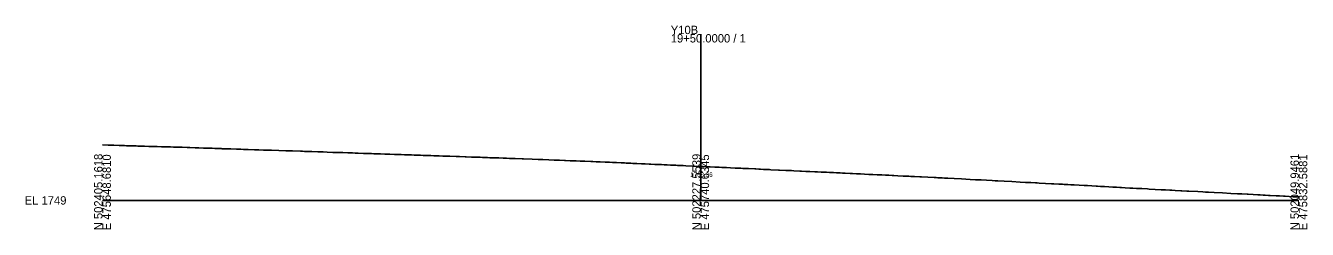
# Model space of a CAD drawing. Extents: x -26 to 1803, y -10 to 9558.
# Drawn here: x -25.7 to 402.8, y 9490.3 to 9558.5 of the extents above; entities that cross this region are included whole.
import ezdxf

# ---------------------------------------------------------------- set-up
doc = ezdxf.new("R2010")
doc.units = 0
for name, color, linetype in [('Exist Cross Section Cell', 7, 'Continuous'), ('Exist XS Center Line Elevation Label', 7, 'Continuous'), ('Exist XS Ground Line', 7, 'Continuous')]:
    doc.layers.add(name, color=color, linetype=linetype)

msp = doc.modelspace()

# ---------------------------------------------------------------- linework, layer by layer
at = {"layer": 'Exist Cross Section Cell'}
for p, q in [((200, 9500), (200, 9555.63)), ((0, 9500), (200, 9500)), ((200, 9500), (400, 9500))]:
    msp.add_line(p, q, dxfattribs=at)
at = {"layer": 'Exist XS Ground Line'}
msp.add_lwpolyline([(0, 9518.54), (1.94, 9518.49), (2.83, 9518.46), (3.78, 9518.43), (5.62, 9518.37), (7.36, 9518.32), (8.07, 9518.3), (8.44, 9518.29), (9.95, 9518.24), (11.27, 9518.2), (11.8, 9518.19), (12.83, 9518.16), (13.64, 9518.13), (14.07, 9518.12), (15.5, 9518.08), (16.91, 9518.04), (17.38, 9518.02), (18.27, 9518), (19.74, 9517.96), (21.27, 9517.91), (22.78, 9517.87), (23.7, 9517.84), (24.78, 9517.81), (25.34, 9517.79), (26.65, 9517.76), (28.33, 9517.7), (29.15, 9517.67), (31, 9517.61), (32.24, 9517.57), (33.79, 9517.52), (34.19, 9517.51), (34.58, 9517.5), (35.93, 9517.46), (36.62, 9517.43), (37.6, 9517.39), (39.27, 9517.33), (39.67, 9517.31), (40.02, 9517.3), (41.46, 9517.26), (42.22, 9517.23), (42.89, 9517.21), (44.86, 9517.14), (45.33, 9517.13), (46.27, 9517.1), (47.2, 9517.07), (48.66, 9517.02), (50.78, 9516.95), (51.4, 9516.93), (52.27, 9516.9), (53.87, 9516.85), (56.47, 9516.77), (58.92, 9516.69), (61.34, 9516.61), (61.92, 9516.59), (63.51, 9516.53), (66.25, 9516.44), (66.87, 9516.42), (67.54, 9516.39), (68.42, 9516.37), (70.02, 9516.31), (71.98, 9516.25), (72.5, 9516.23), (72.88, 9516.22), (73.73, 9516.2), (75.13, 9516.14), (76.96, 9516.08), (77.56, 9516.05), (78.28, 9516.04), (79.16, 9516.02), (80.31, 9515.97), (82.05, 9515.91), (82.68, 9515.88), (83.64, 9515.86), (84.51, 9515.83), (85.52, 9515.79), (87.26, 9515.73), (87.85, 9515.71), (88.99, 9515.68), (89.93, 9515.66), (90.71, 9515.63), (92.38, 9515.56), (92.92, 9515.55), (94.43, 9515.5), (95.31, 9515.47), (96.11, 9515.44), (97.59, 9515.38), (98.52, 9515.36), (98.97, 9515.34), (99.86, 9515.32), (100.95, 9515.28), (101.79, 9515.25), (103.29, 9515.19), (104.17, 9515.17), (104.56, 9515.15), (105.31, 9515.13), (106.34, 9515.09), (107.22, 9515.07), (108.54, 9515.01), (109.78, 9514.98), (110.73, 9514.95), (111.68, 9514.91), (112.6, 9514.88), (113.76, 9514.83), (115.67, 9514.78), (116.18, 9514.76), (118.23, 9514.68), (119.39, 9514.64), (121.26, 9514.59), (121.63, 9514.58), (123.37, 9514.5), (123.87, 9514.49), (126.28, 9514.42), (127.04, 9514.39), (128.71, 9514.32), (129.49, 9514.29), (130.51, 9514.26), (132.49, 9514.19), (133.98, 9514.13), (135.13, 9514.09), (136.08, 9514.06), (137.95, 9513.99), (140.36, 9513.9), (140.76, 9513.89), (143.63, 9513.78), (145.69, 9513.69), (146.38, 9513.67), (147.21, 9513.64), (149.25, 9513.57), (151.01, 9513.49), (152.02, 9513.46), (152.78, 9513.43), (154.5, 9513.37), (154.82, 9513.35), (156.32, 9513.27), (157.65, 9513.24), (158.35, 9513.21), (159.71, 9513.16), (160.35, 9513.13), (160.77, 9513.11), (161.29, 9513.09), (163.28, 9513), (163.9, 9512.98), (165.11, 9512.93), (165.83, 9512.9), (166.35, 9512.88), (168.11, 9512.78), (168.91, 9512.77), (169.47, 9512.74), (170.56, 9512.7), (171.26, 9512.66), (171.88, 9512.64), (173.39, 9512.56), (174.54, 9512.53), (175.04, 9512.51), (176, 9512.47), (176.66, 9512.43), (177.36, 9512.4), (178.63, 9512.33), (180.17, 9512.28), (180.6, 9512.26), (181.44, 9512.22), (182.8, 9512.16), (183.3, 9512.13), (184.72, 9512.06), (185.8, 9512.04), (186.88, 9511.99), (187.82, 9511.93), (188.76, 9511.89), (189.92, 9511.83), (191.73, 9511.76), (192.29, 9511.73), (193.09, 9511.68), (194.17, 9511.63), (195.09, 9511.58), (197.3, 9511.49), (197.74, 9511.47), (199.5, 9511.38), (200, 9511.36), (200.81, 9511.32), (201.95, 9511.26), (202.86, 9511.23), (203.17, 9511.22), (204.76, 9511.14), (206.22, 9511.07), (207.1, 9511.03), (208.61, 9510.97), (209.95, 9510.9), (211.56, 9510.83), (212.21, 9510.8), (213.38, 9510.75), (214.05, 9510.72), (216.04, 9510.62), (218.1, 9510.53), (218.48, 9510.51), (219.39, 9510.47), (220.01, 9510.44), (221.04, 9510.39), (223.05, 9510.29), (223.5, 9510.27), (225.99, 9510.16), (226.3, 9510.14), (228.48, 9510.04), (230.36, 9509.95), (231.1, 9509.91), (233.14, 9509.82), (233.68, 9509.79), (235.18, 9509.72), (235.79, 9509.69), (236.46, 9509.66), (238.17, 9509.58), (239.04, 9509.54), (240.29, 9509.48), (241.23, 9509.44), (242.1, 9509.4), (243.08, 9509.36), (244.37, 9509.29), (245.4, 9509.24), (246.66, 9509.18), (247.37, 9509.14), (247.74, 9509.12), (248.32, 9509.1), (249.96, 9509.02), (250.79, 9508.98), (252.09, 9508.92), (253.38, 9508.86), (254.75, 9508.79), (256.24, 9508.72), (256.83, 9508.69), (257.54, 9508.66), (259, 9508.59), (260.57, 9508.51), (261.81, 9508.45), (262.23, 9508.43), (262.96, 9508.39), (264.06, 9508.34), (264.63, 9508.31), (265.92, 9508.25), (267.71, 9508.16), (268.4, 9508.12), (269.64, 9508.07), (270.27, 9508.03), (271.49, 9507.97), (273.23, 9507.88), (273.83, 9507.85), (275.9, 9507.75), (278.1, 9507.64), (278.7, 9507.61), (279.26, 9507.58), (280.75, 9507.51), (281.52, 9507.47), (282.61, 9507.41), (284.71, 9507.3), (287.15, 9507.18), (290.15, 9507.02), (291.87, 9506.93), (292.77, 9506.88), (293.74, 9506.84), (295.61, 9506.73), (297.46, 9506.63), (298.43, 9506.58), (299.32, 9506.53), (301.52, 9506.41), (304.05, 9506.28), (306.85, 9506.13), (308.57, 9506.03), (309.68, 9505.98), (310.43, 9505.94), (311.89, 9505.86), (312.51, 9505.83), (313.16, 9505.79), (315.3, 9505.68), (317.32, 9505.57), (318.1, 9505.53), (319.7, 9505.44), (320.94, 9505.38), (321.56, 9505.35), (322.76, 9505.29), (323.76, 9505.23), (324.82, 9505.18), (326.57, 9505.08), (328.2, 9505), (328.97, 9504.95), (329.38, 9504.93), (330.83, 9504.85), (332.2, 9504.77), (332.69, 9504.75), (333.64, 9504.7), (335.02, 9504.62), (336.48, 9504.54), (337.82, 9504.46), (339.08, 9504.39), (340.11, 9504.33), (340.65, 9504.3), (341.96, 9504.22), (343.47, 9504.14), (343.83, 9504.12), (344.52, 9504.08), (345.68, 9504.03), (346.29, 9503.99), (347.54, 9503.93), (349.4, 9503.83), (349.94, 9503.8), (351.93, 9503.7), (353.98, 9503.59), (354.71, 9503.55), (355.4, 9503.51), (356.81, 9503.44), (357.54, 9503.4), (358.68, 9503.35), (360.55, 9503.24), (360.86, 9503.22), (362.51, 9503.14), (363.18, 9503.1), (366.25, 9502.93), (367.85, 9502.85), (368.81, 9502.8), (369.8, 9502.75), (371.73, 9502.64), (374.45, 9502.5), (377.29, 9502.34), (379.47, 9502.23), (380.07, 9502.2), (380.94, 9502.15), (382.75, 9502.05), (383.06, 9502.04), (384.73, 9501.95), (386.28, 9501.86), (387.04, 9501.82), (388.09, 9501.77), (388.68, 9501.73), (389.81, 9501.67), (390.43, 9501.64), (392.39, 9501.54), (392.85, 9501.52), (393.51, 9501.49), (394.81, 9501.42), (395.44, 9501.39), (398.09, 9501.25), (400, 9501.16)], dxfattribs=at)

# ---------------------------------------------------------------- texts
at = {"layer": 'Exist Cross Section Cell'}
for s, p in [('Y10B', (190, 9555.63)), ('19+50.0000 / 1', (190, 9552.83)), ('EL 1749', (-26, 9498.6))]:
    msp.add_text(s, height=2.8, dxfattribs=at).set_placement(p)
for s, p in [('N 502405.1618', (0, 9490)), ('E 475648.6810', (2.8, 9490)), ('N 502227.5539', (200, 9490)), ('E 475740.6345', (202.8, 9490)), ('N 502049.9461', (400, 9490)), ('E 475832.5881', (402.8, 9490))]:
    msp.add_text(s, height=2.8, rotation=90, dxfattribs=at).set_placement(p)
at = {"layer": 'Exist XS Center Line Elevation Label'}
msp.add_text('1760.36', height=1.5, dxfattribs=at).set_placement((196.52, 9507.86))

doc.saveas('drawing.dxf')
